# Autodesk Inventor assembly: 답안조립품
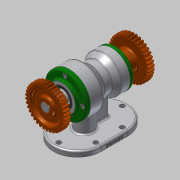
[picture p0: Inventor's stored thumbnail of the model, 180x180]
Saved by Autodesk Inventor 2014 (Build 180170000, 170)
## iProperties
Created: 2020-01
Part Number: 답안조립품
Document SubType Name: Assembly
Designer: kh
Author: kh
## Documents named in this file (13)
- C:\Users\kh\Desktop\700104V1040\답안조립품.iam
- C:\Users\kh\Desktop\700104V1040\본체.ipt
- C:\Users\kh\Desktop\700104V1040\베어링 6203.ipt
- C:\Users\kh\Desktop\700104V1040\베어링 6205.ipt
- C:\Users\kh\Desktop\700104V1040\앞커버.ipt
- C:\Users\kh\Desktop\700104V1040\오일 실 17 30 8.ipt
- C:\Users\kh\Desktop\700104V1040\오일 실 25 38 8.ipt
- C:\Users\kh\Desktop\700104V1040\축.ipt
- C:\Users\kh\Desktop\700104V1040\뒤커버.ipt
- C:\Users\kh\Desktop\700104V1040\멈춤나사 M3.ipt
- C:\Users\kh\Desktop\700104V1040\스퍼기어.ipt
- C:\Users\kh\Desktop\700104V1040\키 5 x 5 x 18.ipt
- C:\Users\kh\Desktop\700104V1040\볼트 M4.ipt
